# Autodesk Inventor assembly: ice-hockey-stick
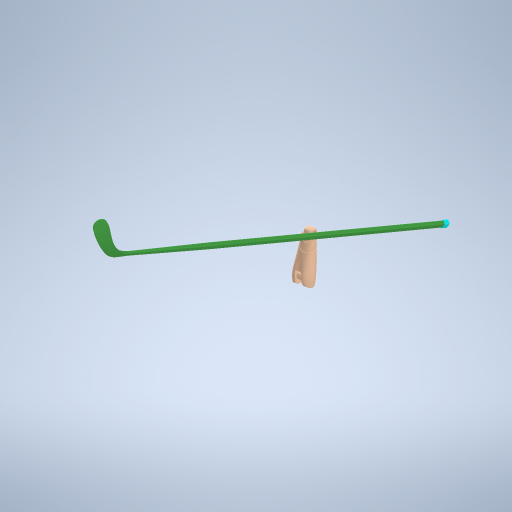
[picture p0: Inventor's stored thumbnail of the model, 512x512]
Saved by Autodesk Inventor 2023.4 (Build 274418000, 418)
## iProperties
Created: 2025-06
Part Number: ice-hockey-stick
Description: STEP AP242
Document SubType Name: Assembly
Designer: bruno
Title: ice-hockey-stick.stp
Preprocessor: Spatial InterOp 3D
Created: 2025-10
Part Number: 1705408627
Material: Générique
Description: PART-1705408627-DESC
Document SubType Name: Modeling
Density: 1 g/cm^3
Appearance: Par défaut
Author: bruno
Revision Number: NONE
Part Number: 1705573034
Description: PART-1705573034-DESC
Created: 2019-10
Part Number: Hand Full-hockey
Designer: yello
Author: yello
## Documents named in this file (8)
- **C:\Users\bruno\Documents\1-Cours-2025-26\1STI2D\ETLV\Diversité et inclusion\Hand Full-hockey.iam*LocalDocs*xAaaaascaAaaaaaaaAaaaqh4lUe*ice-hockey-stick.iam
- **C:\Users\bruno\Documents\1-Cours-2025-26\1STI2D\ETLV\Diversité et inclusion\Hand Full-hockey.iam*LocalDocs*xAaaaqaaaAaaaaaaaAaaaathtDe*1705573034.ipt
- **C:\Users\bruno\Documents\1-Cours-2025-26\1STI2D\ETLV\Diversité et inclusion\Hand Full-hockey.iam*LocalDocs*xAaaaakdaAaaaaaaaAaaaapy50h*1705408627.ipt
- C:\Users\bruno\Documents\1-Cours-2025-26\1STI2D\ETLV\Diversité et inclusion\Hand Full-hockey.iam
- C:\Users\bruno\Documents\1-Cours-2025-26\1STI2D\ETLV\Diversité et inclusion\Prototype 2 (Realistic Hand)\Wrist Rotation.ipt
- C:\Users\bruno\Documents\1-Cours-2025-26\1STI2D\ETLV\Diversité et inclusion\Prototype 2 (Realistic Hand)\Arm to Wrist Connection.ipt
- C:\Users\bruno\Documents\1-Cours-2025-26\1STI2D\ETLV\Diversité et inclusion\Prototype 2 (Realistic Hand)\Arm.ipt
- C:\Users\bruno\Documents\1-Cours-2025-26\1STI2D\ETLV\Diversité et inclusion\Tools\ice-hockey-stick.stp
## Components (4 placed, 4 different names)
1. Wrist Rotation:1 — Mate:1, Mate:2, Mate:4
2. Arm to Wrist Connection:1 — Mate:1, Mate:2, Mate:3
3. Arm:1 — Mate:3, Mate:4
4. ice-hockey-stick:1 [sub-assembly]
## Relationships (4: Mate 4)
- Mate:1: Wrist Rotation:1 ↔ Arm to Wrist Connection:1
- Mate:2: Wrist Rotation:1 ↔ Arm to Wrist Connection:1
- Mate:3: Arm to Wrist Connection:1 ↔ Arm:1
- Mate:4: Wrist Rotation:1 ↔ Arm:1
